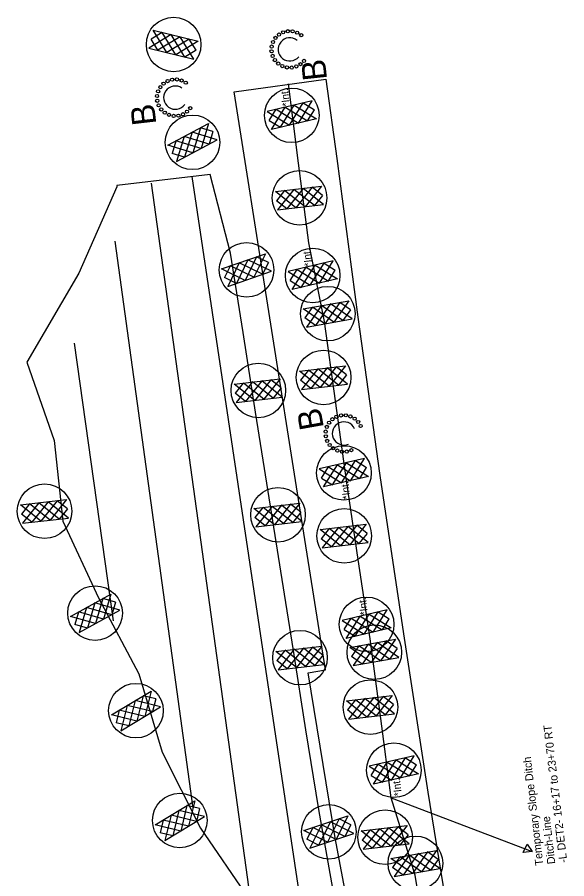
# Model space of a CAD drawing. Extents: x 400935 to 481562, y 415700 to 505362.
# Drawn here: x 478109 to 478452, y 495476 to 496014 of the extents above; entities that cross this region are included whole.
import ezdxf

# ---------------------------------------------------------------- set-up
doc = ezdxf.new("R2010")
doc.units = 0
for name, color, linetype in [('Excelsior Wattle Line Style Final', 7, 'Continuous'), ('Label B Both CELL', 7, 'Continuous'), ('Label B CG CELL', 7, 'Continuous'), ('Label B Final CELL', 7, 'Continuous'), ('Matting on Slope Note Final CELL', 7, 'Continuous'), ('Old_Level_2', 7, 'Continuous'), ('Rock Pipe Inlet Sediment Trap Type B Both CELL', 7, 'Continuous'), ('Rock Pipe Inlet Sediment Trap Type B CG CELL', 7, 'Continuous'), ('Rock Pipe Inlet Sediment Trap Type B Final CELL', 7, 'Continuous'), ('Rock Silt Check Type A with Matting and PAM CG CELL', 7, 'Continuous'), ('Rock Silt Check Type A with Matting and PAM Final CELL', 7, 'Continuous'), ('Scratch_Level_3', 7, 'Continuous'), ('Scratch_Level_4', 7, 'Continuous')]:
    doc.layers.add(name, color=color, linetype=linetype)

msp = doc.modelspace()

# ---------------------------------------------------------------- linework, layer by layer
at = {"layer": 'Excelsior Wattle Line Style Final'}
for p, q in [((478304.55, 495338.54), (478218.42, 495914.81)), ((478255.15, 495461.56), (478193.02, 495910.53)), ((478219.06, 495520.22), (478170.45, 495874.39)), ((478169.33, 495637.05), (478144.99, 495810.7))]:
    msp.add_line(p, q, dxfattribs=at)
at = {"layer": 'Matting on Slope Note Final CELL'}
for p, q in [((478229.76, 495915.9), (478171.44, 495909.17)), ((478171.36, 495908.37), (478147.78, 495854.29)), ((478171.44, 495909.17), (478171.36, 495908.37)), ((478147.78, 495854.29), (478115.21, 495798.76)), ((478115.21, 495798.76), (478132.35, 495749.91)), ((478132.35, 495749.91), (478137.69, 495699.43)), ((478137.69, 495699.43), (478159.99, 495651.44)), ((478159.99, 495651.44), (478185.14, 495604)), ((478185.14, 495604), (478199.83, 495555.06)), ((478199.83, 495555.06), (478223.58, 495507.62)), ((478223.58, 495507.62), (478255.15, 495461.56))]:
    msp.add_line(p, q, dxfattribs=at)
msp.add_lwpolyline([(478372.25, 495176.12), (478359.62, 495224.67), (478347.64, 495273.35), (478336.33, 495322.13), (478325.65, 495371.22), (478315.61, 495420.48), (478306.25, 495469.86), (478297.54, 495519.36), (478289.49, 495568.96), (478281.64, 495618.6), (478273.78, 495668.23), (478265.93, 495717.88), (478258.07, 495767.52), (478250.21, 495817.18), (478242.35, 495866.84), (478229.76, 495915.9)], dxfattribs=at)
at = {"layer": 'Old_Level_2'}
for p, q in [((478293.42, 495961.97), (478265.28, 495955.4)), ((478279.15, 495946.78), (478287.82, 495960.67)), ((478284.8, 495948.1), (478293.42, 495961.97)), ((478287.82, 495960.67), (478294.75, 495956.33)), ((478265.28, 495955.4), (478279.15, 495946.78)), ((478266.58, 495949.75), (478270.93, 495956.72)), ((478267.9, 495944.16), (478276.52, 495958.03)), ((478270.93, 495956.72), (478284.8, 495948.1)), ((478273.55, 495945.46), (478282.17, 495959.35)), ((478276.52, 495958.03), (478290.45, 495949.42)), ((478282.17, 495959.35), (478296.05, 495950.72)), ((478290.48, 495949.48), (478294.75, 495956.33)), ((478266.58, 495949.75), (478273.55, 495945.46)), ((478296.05, 495950.72), (478267.9, 495944.16)), ((478306.48, 495861.96), (478278.33, 495855.39)), ((478280.96, 495844.15), (478289.58, 495858.02)), ((478286.61, 495845.45), (478295.23, 495859.34)), ((478289.58, 495858.02), (478303.5, 495849.41)), ((478292.21, 495846.77), (478300.88, 495860.66)), ((478295.23, 495859.34), (478309.1, 495850.71)), ((478297.86, 495848.09), (478306.48, 495861.96)), ((478300.88, 495860.66), (478307.81, 495856.32)), ((478278.33, 495855.39), (478292.21, 495846.77)), ((478279.64, 495849.74), (478283.98, 495856.71)), ((478283.98, 495856.71), (478297.86, 495848.09)), ((478303.54, 495849.47), (478307.81, 495856.32)), ((478279.64, 495849.74), (478286.61, 495845.45)), ((478309.1, 495850.71), (478280.96, 495844.15)), ((478326, 495738.58), (478297.85, 495732.01)), ((478300.48, 495720.77), (478309.1, 495734.64)), ((478306.13, 495722.07), (478314.75, 495735.96)), ((478309.1, 495734.64), (478323.02, 495726.03)), ((478311.73, 495723.39), (478320.4, 495737.28)), ((478314.75, 495735.96), (478328.62, 495727.34)), ((478317.37, 495724.71), (478326, 495738.58)), ((478320.4, 495737.28), (478327.33, 495732.94)), ((478297.85, 495732.01), (478311.73, 495723.39)), ((478299.16, 495726.36), (478303.5, 495733.33)), ((478303.5, 495733.33), (478317.37, 495724.71)), ((478323.06, 495726.09), (478327.33, 495732.94)), ((478299.16, 495726.36), (478306.13, 495722.07)), ((478328.62, 495727.34), (478300.48, 495720.77)), ((478340.15, 495644), (478312.01, 495637.43)), ((478325.88, 495628.81), (478334.55, 495642.69)), ((478331.53, 495630.13), (478340.15, 495644)), ((478334.55, 495642.69), (478341.48, 495638.35)), ((478312.01, 495637.43), (478325.88, 495628.81)), ((478313.31, 495631.78), (478317.66, 495638.75)), ((478314.63, 495626.18), (478323.25, 495640.06)), ((478317.66, 495638.75), (478331.53, 495630.13)), ((478320.28, 495627.49), (478328.9, 495641.37)), ((478323.25, 495640.06), (478337.18, 495631.45)), ((478328.9, 495641.37), (478342.78, 495632.75)), ((478337.21, 495631.51), (478341.48, 495638.35)), ((478313.31, 495631.78), (478320.28, 495627.49)), ((478342.78, 495632.75), (478314.63, 495626.18)), ((478357.15, 495552.84), (478329.01, 495546.27)), ((478342.88, 495537.65), (478351.55, 495551.53)), ((478348.53, 495538.97), (478357.15, 495552.84)), ((478351.55, 495551.53), (478358.48, 495547.19)), ((478329.01, 495546.27), (478342.88, 495537.65)), ((478330.31, 495540.62), (478334.66, 495547.59)), ((478331.63, 495535.02), (478340.26, 495548.89)), ((478334.66, 495547.59), (478348.53, 495538.97)), ((478337.28, 495536.33), (478345.9, 495550.21)), ((478340.26, 495548.89), (478354.18, 495540.28)), ((478345.9, 495550.21), (478359.78, 495541.59)), ((478354.21, 495540.34), (478358.48, 495547.19)), ((478330.31, 495540.62), (478337.28, 495536.33)), ((478359.78, 495541.59), (478331.63, 495535.02))]:
    msp.add_line(p, q, dxfattribs=at)
for centre in [(478280.65, 495952.93), (478293.71, 495852.92), (478313.23, 495729.54), (478327.38, 495634.96), (478344.38, 495543.8)]:
    msp.add_circle(centre, 17.04, dxfattribs=at)
at = {"layer": 'Rock Pipe Inlet Sediment Trap Type B Both CELL'}
for centre in [(478272.66, 496003.39), (478275.28, 496004.81), (478278.18, 496005.51), (478281.16, 496005.43), (478284.02, 496004.59), (478286.57, 496003.03), (478268.94, 495998.79), (478270.5, 496001.33), (478268.02, 495992.95), (478268.1, 495995.93), (478268.72, 495990.05), (478270.15, 495987.43), (478288.27, 495986.97), (478272.2, 495985.27), (478274.74, 495983.71), (478277.6, 495982.87), (478280.59, 495982.79), (478283.48, 495983.49), (478286.1, 495984.91)]:
    msp.add_circle(centre, 1.01, dxfattribs=at)
msp.add_arc((478279.38, 495994.15), 7.26, 51.042, 321.0332, dxfattribs=at)
at = {"layer": 'Rock Pipe Inlet Sediment Trap Type B CG CELL'}
for centre in [(478311.42, 495765.49), (478314.4, 495765.56), (478303.97, 495760.93), (478306.02, 495763.09), (478308.56, 495764.64), (478317.3, 495764.87), (478319.92, 495763.44), (478322.09, 495761.39), (478301.84, 495755.41), (478302.54, 495758.31), (478323.64, 495758.84), (478301.92, 495752.42), (478302.76, 495749.56), (478304.32, 495747.02), (478306.48, 495744.97), (478317.84, 495743.76), (478309.1, 495743.54), (478312, 495742.84), (478314.98, 495742.92)]:
    msp.add_circle(centre, 1.01, dxfattribs=at)
msp.add_arc((478313.2, 495754.2), 7.26, 23.9657, 293.9569, dxfattribs=at)
at = {"layer": 'Rock Pipe Inlet Sediment Trap Type B Final CELL'}
for centre in [(478205.95, 495975.24), (478208.93, 495975.37), (478198.57, 495970.56), (478200.59, 495972.75), (478203.1, 495974.35), (478211.84, 495974.72), (478214.48, 495973.34), (478196.54, 495965), (478197.19, 495967.92), (478196.66, 495962.03), (478197.55, 495959.18), (478199.15, 495956.66), (478201.34, 495954.64), (478212.72, 495953.63), (478215.24, 495955.22), (478217.26, 495957.42), (478203.99, 495953.26), (478206.9, 495952.61), (478209.88, 495952.74)]:
    msp.add_circle(centre, 1.01, dxfattribs=at)
msp.add_arc((478207.91, 495963.99), 7.26, 54.9038, 324.895, dxfattribs=at)
at = {"layer": 'Rock Silt Check Type A with Matting and PAM CG CELL'}
for p, q in [((478287.85, 495832.05), (478316.3, 495837.12)), ((478316.3, 495837.12), (478306.96, 495823.72)), ((478301.25, 495822.7), (478287.85, 495832.05)), ((478293.47, 495833), (478288.85, 495826.39)), ((478299.22, 495834.07), (478289.87, 495820.68)), ((478306.96, 495823.72), (478293.51, 495833.06)), ((478304.93, 495835.09), (478295.54, 495821.69)), ((478312.62, 495824.73), (478299.22, 495834.07)), ((478310.59, 495836.11), (478301.25, 495822.7)), ((478318.33, 495825.75), (478304.93, 495835.09)), ((478317.32, 495831.46), (478310.59, 495836.11)), ((478317.32, 495831.46), (478312.62, 495824.73)), ((478295.54, 495821.69), (478288.85, 495826.39)), ((478289.87, 495820.68), (478318.33, 495825.75)), ((478316.93, 495620.54), (478345.38, 495625.61)), ((478322.55, 495621.49), (478317.92, 495614.88)), ((478328.3, 495622.57), (478318.95, 495609.17)), ((478336.03, 495612.21), (478322.59, 495621.55)), ((478334.01, 495623.58), (478324.61, 495610.18)), ((478341.7, 495613.22), (478328.3, 495622.57)), ((478339.67, 495624.6), (478330.32, 495611.2)), ((478347.41, 495614.24), (478334.01, 495623.58)), ((478345.38, 495625.61), (478336.03, 495612.21)), ((478346.4, 495619.95), (478339.67, 495624.6)), ((478330.32, 495611.2), (478316.93, 495620.54)), ((478346.4, 495619.95), (478341.7, 495613.22)), ((478324.61, 495610.18), (478317.92, 495614.88)), ((478318.95, 495609.17), (478347.41, 495614.24)), ((478342.56, 495488.7), (478371.02, 495493.77)), ((478365.3, 495492.76), (478355.96, 495479.35)), ((478371.02, 495493.77), (478361.67, 495480.37)), ((478372.04, 495488.11), (478365.3, 495492.76)), ((478355.96, 495479.35), (478342.56, 495488.7)), ((478348.18, 495489.65), (478343.56, 495483.04)), ((478353.93, 495490.73), (478344.59, 495477.33)), ((478361.67, 495480.37), (478348.22, 495489.71)), ((478359.64, 495491.74), (478350.25, 495478.34)), ((478367.33, 495481.38), (478353.93, 495490.73)), ((478373.04, 495482.4), (478359.64, 495491.74)), ((478372.04, 495488.11), (478367.33, 495481.38)), ((478350.25, 495478.34), (478343.56, 495483.04)), ((478344.59, 495477.33), (478373.04, 495482.4))]:
    msp.add_line(p, q, dxfattribs=at)
for centre in [(478303.11, 495829.03), (478332.19, 495617.52), (478357.82, 495485.68)]:
    msp.add_circle(centre, 17.04, dxfattribs=at)
at = {"layer": 'Rock Silt Check Type A with Matting and PAM Final CELL'}
for p, q in [((478205.4, 496003.38), (478191.41, 495994.95)), ((478199.71, 496004.74), (478192.8, 496000.59)), ((478194.19, 496006.16), (478222.24, 495999.21)), ((478202.62, 495992.17), (478194.19, 496006.16)), ((478208.25, 495990.78), (478199.77, 496004.78)), ((478213.83, 495989.39), (478205.4, 496003.38)), ((478196.99, 495993.57), (478192.8, 496000.59)), ((478211.03, 496001.99), (478196.99, 495993.57)), ((478216.62, 496000.61), (478202.62, 495992.17)), ((478222.24, 495999.21), (478208.25, 495990.78)), ((478219.46, 495988), (478211.03, 496001.99)), ((478220.87, 495993.62), (478216.62, 496000.61)), ((478191.41, 495994.95), (478219.46, 495988)), ((478220.87, 495993.62), (478213.83, 495989.39)), ((478203.24, 495934.24), (478228.75, 495947.83)), ((478223.63, 495945.11), (478218.87, 495929.48)), ((478231.46, 495942.76), (478223.63, 495945.11)), ((478228.75, 495947.83), (478223.99, 495932.21)), ((478213.44, 495939.67), (478208.67, 495924.05)), ((478229.06, 495934.91), (478213.44, 495939.67)), ((478218.56, 495942.4), (478213.75, 495926.75)), ((478234.18, 495937.64), (478218.56, 495942.4)), ((478231.46, 495942.76), (478229.06, 495934.91)), ((478218.87, 495929.48), (478203.24, 495934.24)), ((478208.3, 495936.88), (478205.93, 495929.16)), ((478223.99, 495932.21), (478208.32, 495936.95)), ((478208.67, 495924.05), (478234.18, 495937.64)), ((478213.75, 495926.75), (478205.93, 495929.16)), ((478270.47, 495905.34), (478299.18, 495908.66)), ((478281.95, 495906.67), (478271.8, 495893.86)), ((478287.71, 495907.33), (478277.52, 495894.52)), ((478294.75, 495896.52), (478281.95, 495906.67)), ((478293.42, 495908.01), (478283.28, 495895.19)), ((478300.51, 495897.19), (478287.71, 495907.33)), ((478299.18, 495908.66), (478289.04, 495895.86)), ((478299.86, 495902.95), (478293.42, 495908.01)), ((478283.28, 495895.19), (478270.47, 495905.34)), ((478276.14, 495905.94), (478271.12, 495899.62)), ((478289.04, 495895.86), (478276.19, 495906)), ((478299.86, 495902.95), (478294.75, 495896.52)), ((478277.52, 495894.52), (478271.12, 495899.62)), ((478271.8, 495893.86), (478300.51, 495897.19)), ((478236.86, 495856.99), (478264.17, 495866.46)), ((478258.69, 495864.57), (478251.56, 495849.86)), ((478264.17, 495866.46), (478257.04, 495851.76)), ((478266.06, 495861.03), (478258.69, 495864.57)), ((478242.27, 495858.81), (478238.74, 495851.55)), ((478247.78, 495860.77), (478240.65, 495846.08)), ((478257.04, 495851.76), (478242.3, 495858.87)), ((478253.26, 495862.67), (478246.08, 495847.96)), ((478262.47, 495853.65), (478247.78, 495860.77)), ((478267.95, 495855.55), (478253.26, 495862.67)), ((478266.06, 495861.03), (478262.47, 495853.65)), ((478251.56, 495849.86), (478236.86, 495856.99)), ((478240.65, 495846.08), (478267.95, 495855.55)), ((478246.08, 495847.96), (478238.74, 495851.55)), ((478285.48, 495793.16), (478314.19, 495796.49)), ((478298.28, 495783.02), (478285.48, 495793.16)), ((478291.15, 495793.77), (478286.13, 495787.45)), ((478296.95, 495794.49), (478286.81, 495781.69)), ((478304.04, 495783.69), (478291.19, 495793.83)), ((478302.71, 495795.16), (478292.52, 495782.35)), ((478309.75, 495784.35), (478296.95, 495794.49)), ((478308.42, 495795.84), (478298.28, 495783.02)), ((478315.52, 495785.02), (478302.71, 495795.16)), ((478314.19, 495796.49), (478304.04, 495783.69)), ((478314.86, 495790.78), (478308.42, 495795.84)), ((478244.71, 495785.04), (478273.42, 495788.37)), ((478273.42, 495788.37), (478263.27, 495775.56)), ((478314.86, 495790.78), (478309.75, 495784.35)), ((478257.51, 495774.9), (478244.71, 495785.04)), ((478250.38, 495785.65), (478245.36, 495779.33)), ((478256.18, 495786.37), (478246.04, 495773.57)), ((478263.27, 495775.56), (478250.42, 495785.7)), ((478261.95, 495787.04), (478251.75, 495774.23)), ((478268.99, 495776.23), (478256.18, 495786.37)), ((478267.66, 495787.71), (478257.51, 495774.9)), ((478274.75, 495776.89), (478261.95, 495787.04)), ((478274.09, 495782.66), (478267.66, 495787.71)), ((478274.09, 495782.66), (478268.99, 495776.23)), ((478292.52, 495782.35), (478286.13, 495787.45)), ((478286.81, 495781.69), (478315.52, 495785.02)), ((478251.75, 495774.23), (478245.36, 495779.33)), ((478246.04, 495773.57), (478274.75, 495776.89)), ((478111.27, 495709.54), (478139.97, 495712.87)), ((478139.97, 495712.87), (478129.83, 495700.06)), ((478124.07, 495699.4), (478111.27, 495709.54)), ((478116.93, 495710.15), (478111.92, 495703.83)), ((478122.74, 495710.87), (478112.6, 495698.07)), ((478129.83, 495700.06), (478116.98, 495710.2)), ((478128.5, 495711.54), (478118.31, 495698.73)), ((478135.54, 495700.72), (478122.74, 495710.87)), ((478134.21, 495712.21), (478124.07, 495699.4)), ((478141.3, 495701.39), (478128.5, 495711.54)), ((478140.65, 495707.15), (478134.21, 495712.21)), ((478140.65, 495707.15), (478135.54, 495700.72)), ((478256.99, 495707.35), (478285.7, 495710.67)), ((478269.79, 495697.2), (478256.99, 495707.35)), ((478262.66, 495707.96), (478257.64, 495701.64)), ((478268.47, 495708.68), (478258.32, 495695.88)), ((478275.56, 495697.87), (478262.7, 495708.01)), ((478274.23, 495709.35), (478264.03, 495696.54)), ((478281.27, 495698.53), (478268.47, 495708.68)), ((478279.94, 495710.02), (478269.79, 495697.2)), ((478287.03, 495699.2), (478274.23, 495709.35)), ((478285.7, 495710.67), (478275.56, 495697.87)), ((478286.37, 495704.96), (478279.94, 495710.02)), ((478118.31, 495698.73), (478111.92, 495703.83)), ((478286.37, 495704.96), (478281.27, 495698.53)), ((478112.6, 495698.07), (478141.3, 495701.39)), ((478264.03, 495696.54), (478257.64, 495701.64)), ((478258.32, 495695.88), (478287.03, 495699.2)), ((478298.34, 495694.18), (478327.05, 495697.5)), ((478321.29, 495696.85), (478311.15, 495684.03)), ((478327.05, 495697.5), (478316.91, 495684.7)), ((478327.73, 495691.79), (478321.29, 495696.85)), ((478311.15, 495684.03), (478298.34, 495694.18)), ((478304.01, 495694.78), (478298.99, 495688.46)), ((478309.82, 495695.51), (478299.67, 495682.7)), ((478316.91, 495684.7), (478304.06, 495694.84)), ((478315.58, 495696.17), (478305.38, 495683.37)), ((478322.62, 495685.36), (478309.82, 495695.51)), ((478328.38, 495686.03), (478315.58, 495696.17)), ((478327.73, 495691.79), (478322.62, 495685.36)), ((478305.38, 495683.37), (478298.99, 495688.46)), ((478299.67, 495682.7), (478328.38, 495686.03)), ((478142.42, 495639.96), (478167.74, 495653.9)), ((478167.74, 495653.9), (478163.19, 495638.21)), ((478157.62, 495648.33), (478153.03, 495632.61)), ((478173.31, 495643.78), (478157.62, 495648.33)), ((478162.65, 495651.11), (478158.11, 495635.41)), ((478170.52, 495648.87), (478162.65, 495651.11)), ((478170.52, 495648.87), (478168.23, 495640.98)), ((478147.44, 495642.66), (478145.19, 495634.91)), ((478163.19, 495638.21), (478147.46, 495642.73)), ((478152.54, 495645.53), (478148, 495629.84)), ((478148, 495629.84), (478173.31, 495643.78)), ((478168.23, 495640.98), (478152.54, 495645.53)), ((478158.11, 495635.41), (478142.42, 495639.96)), ((478153.03, 495632.61), (478145.19, 495634.91)), ((478270.75, 495618.07), (478299.45, 495621.39)), ((478299.45, 495621.39), (478289.31, 495608.59)), ((478283.55, 495607.92), (478270.75, 495618.07)), ((478276.41, 495618.67), (478271.4, 495612.35)), ((478282.22, 495619.4), (478272.07, 495606.59)), ((478289.31, 495608.59), (478276.46, 495618.73)), ((478287.98, 495620.06), (478277.79, 495607.26)), ((478295.02, 495609.25), (478282.22, 495619.4)), ((478293.69, 495620.74), (478283.55, 495607.92)), ((478300.78, 495609.92), (478287.98, 495620.06)), ((478300.13, 495615.68), (478293.69, 495620.74)), ((478300.13, 495615.68), (478295.02, 495609.25)), ((478277.79, 495607.26), (478271.4, 495612.35)), ((478272.07, 495606.59), (478300.78, 495609.92)), ((478168.04, 495578.41), (478192.8, 495593.31)), ((478187.82, 495590.33), (478183.89, 495574.47)), ((478195.78, 495588.39), (478187.82, 495590.33)), ((478192.8, 495593.31), (478188.86, 495577.46)), ((478314.72, 495587.22), (478343.43, 495590.54)), ((478331.96, 495589.21), (478321.76, 495576.41)), ((478337.67, 495589.89), (478327.52, 495577.07)), ((478344.76, 495579.07), (478331.96, 495589.21)), ((478343.43, 495590.54), (478333.28, 495577.74)), ((478344.1, 495584.83), (478337.67, 495589.89)), ((478177.93, 495584.36), (478173.99, 495568.51)), ((478173.99, 495568.51), (478198.76, 495583.41)), ((478193.79, 495580.42), (478177.93, 495584.36)), ((478182.9, 495587.35), (478178.92, 495571.48)), ((478198.76, 495583.41), (478182.9, 495587.35)), ((478195.78, 495588.39), (478193.79, 495580.42)), ((478327.52, 495577.07), (478314.72, 495587.22)), ((478320.39, 495587.82), (478315.37, 495581.5)), ((478326.19, 495588.55), (478316.05, 495575.74)), ((478333.28, 495577.74), (478320.43, 495587.88)), ((478339, 495578.4), (478326.19, 495588.55)), ((478344.1, 495584.83), (478339, 495578.4)), ((478183.89, 495574.47), (478168.04, 495578.41)), ((478172.95, 495581.3), (478170.99, 495573.47)), ((478188.86, 495577.46), (478172.96, 495581.37)), ((478321.76, 495576.41), (478315.37, 495581.5)), ((478316.05, 495575.74), (478344.76, 495579.07)), ((478178.92, 495571.48), (478170.99, 495573.47)), ((478195.43, 495509.7), (478220.11, 495524.74)), ((478220.11, 495524.74), (478216.26, 495508.87)), ((478210.24, 495518.73), (478206.35, 495502.83)), ((478226.12, 495514.88), (478210.24, 495518.73)), ((478215.15, 495521.73), (478211.3, 495505.85)), ((478223.11, 495519.84), (478215.15, 495521.73)), ((478223.11, 495519.84), (478221.17, 495511.86)), ((478205.29, 495515.71), (478201.44, 495499.84)), ((478201.44, 495499.84), (478226.12, 495514.88)), ((478221.17, 495511.86), (478205.29, 495515.71)), ((478288.28, 495506.17), (478315.72, 495515.23)), ((478310.21, 495513.42), (478302.87, 495498.82)), ((478315.72, 495515.23), (478308.38, 495500.64)), ((478317.54, 495509.77), (478310.21, 495513.42)), ((478211.3, 495505.85), (478195.43, 495509.7)), ((478200.32, 495512.62), (478198.41, 495504.78)), ((478216.26, 495508.87), (478200.34, 495512.69)), ((478293.71, 495507.91), (478290.07, 495500.71)), ((478299.25, 495509.79), (478291.9, 495495.2)), ((478308.38, 495500.64), (478293.74, 495507.97)), ((478304.76, 495511.61), (478297.36, 495497.01)), ((478313.84, 495502.44), (478299.25, 495509.79)), ((478319.34, 495504.26), (478304.76, 495511.61)), ((478317.54, 495509.77), (478313.84, 495502.44)), ((478323.88, 495505.89), (478352.59, 495509.21)), ((478346.82, 495508.56), (478336.68, 495495.74)), ((478352.59, 495509.21), (478342.44, 495496.41)), ((478353.26, 495503.5), (478346.82, 495508.56)), ((478206.35, 495502.83), (478198.41, 495504.78)), ((478302.87, 495498.82), (478288.28, 495506.17)), ((478291.9, 495495.2), (478319.34, 495504.26)), ((478336.68, 495495.74), (478323.88, 495505.89)), ((478329.55, 495506.5), (478324.53, 495500.18)), ((478335.35, 495507.22), (478325.21, 495494.42)), ((478342.44, 495496.41), (478329.59, 495506.55)), ((478341.11, 495507.89), (478330.92, 495495.08)), ((478348.16, 495497.07), (478335.35, 495507.22)), ((478353.92, 495497.74), (478341.11, 495507.89)), ((478353.26, 495503.5), (478348.16, 495497.07)), ((478297.36, 495497.01), (478290.07, 495500.71)), ((478330.92, 495495.08), (478324.53, 495500.18)), ((478325.21, 495494.42), (478353.92, 495497.74))]:
    msp.add_line(p, q, dxfattribs=at)
for centre in [(478206.9, 495997.19), (478218.69, 495936.07), (478285.52, 495901.39), (478252.41, 495856.4), (478300.52, 495789.22), (478259.76, 495781.1), (478126.31, 495705.6), (478272.04, 495703.41), (478313.39, 495690.23), (478157.84, 495642), (478285.79, 495614.12), (478329.77, 495583.28), (478183.37, 495581.04), (478210.74, 495512.42), (478303.81, 495505.35), (478338.93, 495501.95)]:
    msp.add_circle(centre, 17.04, dxfattribs=at)
at = {"layer": 'Scratch_Level_3'}
for points in [[(478399.7, 495231.61), (478391.17, 495280.88), (478382.65, 495330.15), (478374.18, 495379.47), (478365.88, 495428.84), (478357.76, 495478.23), (478342.8, 495526.54), (478336.27, 495576.21), (478329.54, 495625.84), (478322.14, 495675.37), (478314.92, 495724.92), (478307.88, 495774.5), (478301.03, 495824.11), (478291.38, 495873.34), (478284.88, 495923.01), (478278.56, 495972.69)], [(478342.8, 495526.54), (478430.77, 495492.98), (478425.15, 495492.48), (478427.62, 495497.56), (478430.77, 495492.98)]]:
    msp.add_lwpolyline(points, dxfattribs=at)
at = {"layer": 'Scratch_Level_4'}
msp.add_lwpolyline([(478244.61, 495967.71), (478301.97, 495975.5), (478308.68, 495926.08), (478321.83, 495826.95), (478335.71, 495727.91), (478350.31, 495628.98), (478365.62, 495530.17), (478381.66, 495431.46), (478398.32, 495333.25), (478415.69, 495233.03), (478377.63, 495226.87), (478367.06, 495224.86), (478347.56, 495305.22), (478326.25, 495403.04), (478307.74, 495501.63), (478294.56, 495581.71), (478290.91, 495604.76), (478301.78, 495606.48), (478294.49, 495652.56), (478286.82, 495701.03)], close=True, dxfattribs=at)

# ---------------------------------------------------------------- texts
at = {"layer": 'Label B Both CELL'}
msp.add_text('B', height=15, rotation=96.0426, dxfattribs=at).set_placement((478302.72, 495975.37))
at = {"layer": 'Label B CG CELL'}
msp.add_text('B', height=15, rotation=100.0978, dxfattribs=at).set_placement((478300.76, 495757.8))
at = {"layer": 'Label B Final CELL'}
msp.add_text('B', height=15, rotation=96.6074, dxfattribs=at).set_placement((478196.16, 495947.48))
at = {"layer": 'Old_Level_2'}
for p in [(478279.5, 495958.78), (478293.39, 495858.81), (478317.25, 495713.33), (478328.19, 495640.91), (478349.37, 495527.89)]:
    msp.add_text('*Int.', height=4.746, rotation=96.6074, dxfattribs=at).set_placement(p)
at = {"layer": 'Scratch_Level_3'}
for s, p in [('-L DET2- 16+17 to 23+70 RT', (478452.64, 495486.29)), ('Temporary Slope Ditch', (478437.74, 495484.56)), ('Ditch-Line', (478445.19, 495485.43))]:
    msp.add_text(s, height=5, rotation=96.6074, dxfattribs=at).set_placement(p)

doc.saveas('drawing.dxf')
